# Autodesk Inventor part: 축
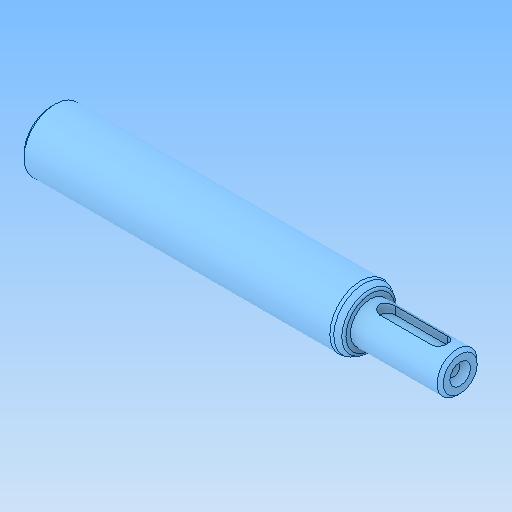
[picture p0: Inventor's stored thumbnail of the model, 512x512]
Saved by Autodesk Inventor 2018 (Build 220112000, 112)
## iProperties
Created: 2024-09
Part Number: 축
Material: 강철, 탄소
Document SubType Name: Modeling
Designer: home
Density: 7.85 g/cm^3
Appearance: 기본값
Author: jhkim
Sending System: Autodesk Inventor 2025
Preprocessor: ST-DEVELOPER v20
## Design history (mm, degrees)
feature "솔리드1"
node "솔리드2"
